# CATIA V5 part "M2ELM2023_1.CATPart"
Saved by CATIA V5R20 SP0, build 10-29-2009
Part number: M2ELM2022_2
Bounding box of the stored display mesh (mm): x -59.975 to 59.975, y -59.975 to 59.975, z 0 to 65
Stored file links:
  E:\0 Pedagogie\01 Hamma Lakhdar University\0Pedagogie\2023 2024\M2ELM CFAO\Travail a domicile 3\M2ELM2023_1.CATPart
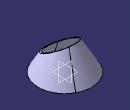
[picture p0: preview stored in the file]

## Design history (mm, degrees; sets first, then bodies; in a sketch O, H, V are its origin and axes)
Body1 (main body)
  Sketch1 on yz-plane, origin (0, 0, 0), H (0, 1, 0), V (0, 0, 1)
    line L1 (0, 0) -> (60, 0)
    line L2 (60, 0) -> (0, 103.923)
    point P2 (0, 103.923)
    line L3 (0, 103.923) -> (0, 0)
    length L1 = 60
    angle L2 L1 = 60
    horizontal: L1 H
    coincidence: P2 V
    vertical: L3 V
  Shaft1: profile Sketch1, axis Sketch1.L3, angle 360
  Shell1: IntOffset 2, Face face of Shaft1 from Sketch1.L1, ExtOffset 0
  Sketch2 on yz-plane, origin (0, 0, 0), H (0, 1, 0), V (0, 0, 1)
    line L1 (-55.5087, 20) -> (51.4958, 81.7791)
    point P1 (-55.5087, 20)
    line L2 (51.4958, 81.7791) -> (-2.8528, 152.8165)
    line L3 (-2.8528, 152.8165) -> (-55.5087, 152.8165)
    line L4 (-55.5087, 152.8165) -> (-55.5087, 20)
    reference projected line E1 (60, 0) -> (-60, 0) from edge [face of Shaft1 from Sketch1.L2 | face of Shaft1 from Sketch1.L1]
    reference projected line E2 (60, 0) -> (-60, 0) from edge [face of Shaft1 from Sketch1.L2 | face of Shaft1 from Sketch1.L1]
    angle L1 E1 = 30
    distance P1 E2 = 20
    horizontal: L3 H
    vertical: L4 V
  Pocket1: profile Sketch2, direction (1, 0, 0), length 35, mirrored extent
